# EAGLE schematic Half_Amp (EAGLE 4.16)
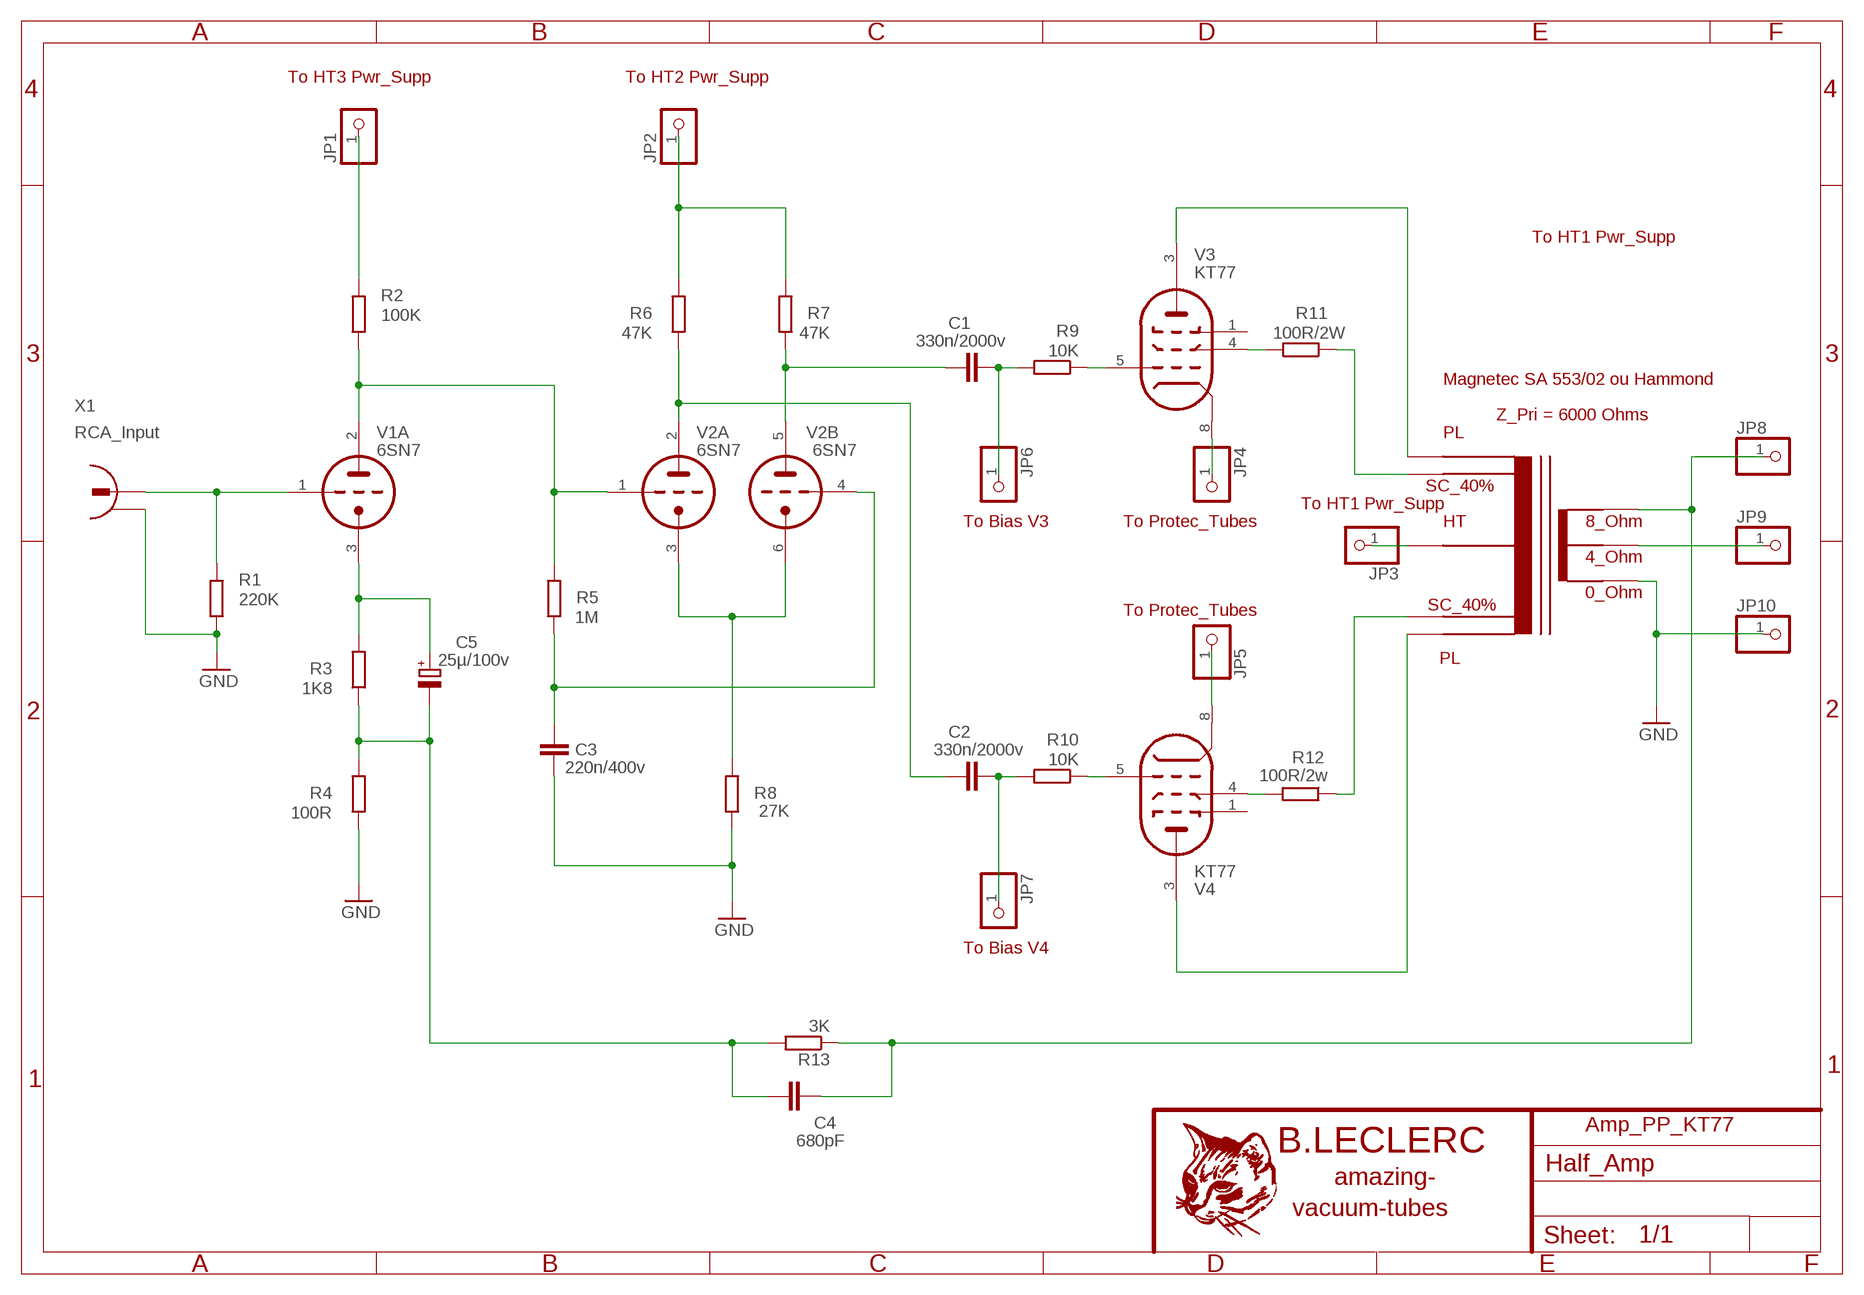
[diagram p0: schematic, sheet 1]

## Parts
C1  330n/2000v  C-EU050-030X075  [C050-030X075]
C2  330n/2000v  C-EU050-030X075  [C050-030X075]
C3  220n/400v  C-EU050-030X075  [C050-030X075]
C4  680pF  C-EU050-030X075  [C050-030X075]
C5  25µ/100v  CPOL-EUE3.5-10  [E3,5-10]
JP1  PINHD-1X1  [1X01]
JP2  PINHD-1X1  [1X01]
JP3  PINHD-1X1  [1X01]
JP4  PINHD-1X1  [1X01]
JP5  PINHD-1X1  [1X01]
JP6  PINHD-1X1  [1X01]
JP7  PINHD-1X1  [1X01]
JP8  PINHD-1X1  [1X01]
JP9  PINHD-1X1  [1X01]
JP10  PINHD-1X1  [1X01]
R1  220K  R-EU_0207/12  [0207/12]
R2  100K  R-EU_0207/12  [0207/12]
R3  1K8  R-EU_0207/12  [0207/12]
R4  100R  R-EU_0207/12  [0207/12]
R5  1M  R-EU_0207/12  [0207/12]
R6  47K  R-EU_0207/12  [0207/12]
R7  47K  R-EU_0207/12  [0207/12]
R8  27K  R-EU_0207/12  [0207/12]
R9  10K  R-EU_0207/12  [0207/12]
R10  10K  R-EU_0207/12  [0207/12]
R11  100R/2W  R-EU_0207/12  [0207/12]
R12  100R/2w  R-EU_0207/12  [0207/12]
R13  3K  R-EU_0207/12  [0207/12]
U$2  OUT_AUDIO  [OUT_AUDIO]
V1  6SN7  6SN7GT-P  [OKTAL]
V2  6SN7  6SN7GT-P  [OKTAL]
V3  KT77  KT77-P  [OKTAL]
V4  KT77  KT77-P  [OKTAL]
X1  RCA_Input  736880-49  [736880-49]

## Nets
GND: C3.1 JP10.1 R1.1 R4.1 R8.1 U$2.P$8 X1.2
N$1: R1.2 V1.1(A:TG) X1.1
N$2: JP1.1 R2.2
N$3: R2.1 R5.2 V1.2(A:TA) V2.1(A:TG)
N$4: C5.+ R3.2 V1.3(A:TK)
N$5: C4.2 C5.- R3.1 R4.2 R13.2
N$6: C3.2 R5.1 V2.4(B:TG)
N$7: R8.2 V2.3(A:TK) V2.6(B:TK)
N$8: JP3.1 U$2.P$2
N$9: JP2.1 R6.2 R7.2
N$10: C2.1 R6.1 V2.2(A:TA)
N$11: C1.1 R7.1 V2.5(B:TA)
N$12: R11.1 U$2.P$5
N$13: C1.2 JP6.1 R9.2
N$14: R9.1 V3.5(PG)
N$15: C2.2 JP7.1 R10.2
N$16: R10.1 V4.5(PG)
N$17: R11.2 V3.4(PSG)
N$18: R12.2 V4.4(PSG)
N$19: JP5.1 V4.8(PK)
N$20: JP4.1 V3.8(PK)
N$21: U$2.P$1 V3.3(PA)
N$22: R12.1 U$2.P$4
N$23: U$2.P$3 V4.3(PA)
N$25: JP9.1 U$2.P$7
N$26: C4.1 JP8.1 R13.1 U$2.P$6
Unconnected: V1.4(B:TG) V1.5(B:TA) V1.6(B:TK) V1.7(":H1) V1.8(":H2) V2.7(":H1) V2.8(":H2) V3.1(PBG) V3.2(H1) V3.7(H2) V4.1(PBG) V4.2(H1) V4.7(H2) X1.2@2

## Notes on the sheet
- To HT3 Pwr_Supp | To HT2 Pwr_Supp
- To HT1 Pwr_Supp
- Magnetec SA 553/02 ou Hammond
- Z_Pri = 6000 Ohms
- To HT1 Pwr_Supp
- To Bias V3 | To Protec_Tubes
- To Protec_Tubes
- To Bias V4
- Amp_PP_KT77

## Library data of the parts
C1-C4 = rcl:C-EU: CAPACITOR, European symbol
C5 = rcl:CPOL-EU: POLARIZED CAPACITOR, European symbol
JP1-JP10 = pinhead:PINHD-1X1: PIN HEADER
R1-R13 = rcl:R-EU_: RESISTOR, European symbol
U$2 = trafo:OUT_AUDIO
V1 V2 = tubes:6SN7GT-P
V3 V4 = tubes:KT77-P
X1 = con-conrad:736880-49: Cinch Connector (Jack)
